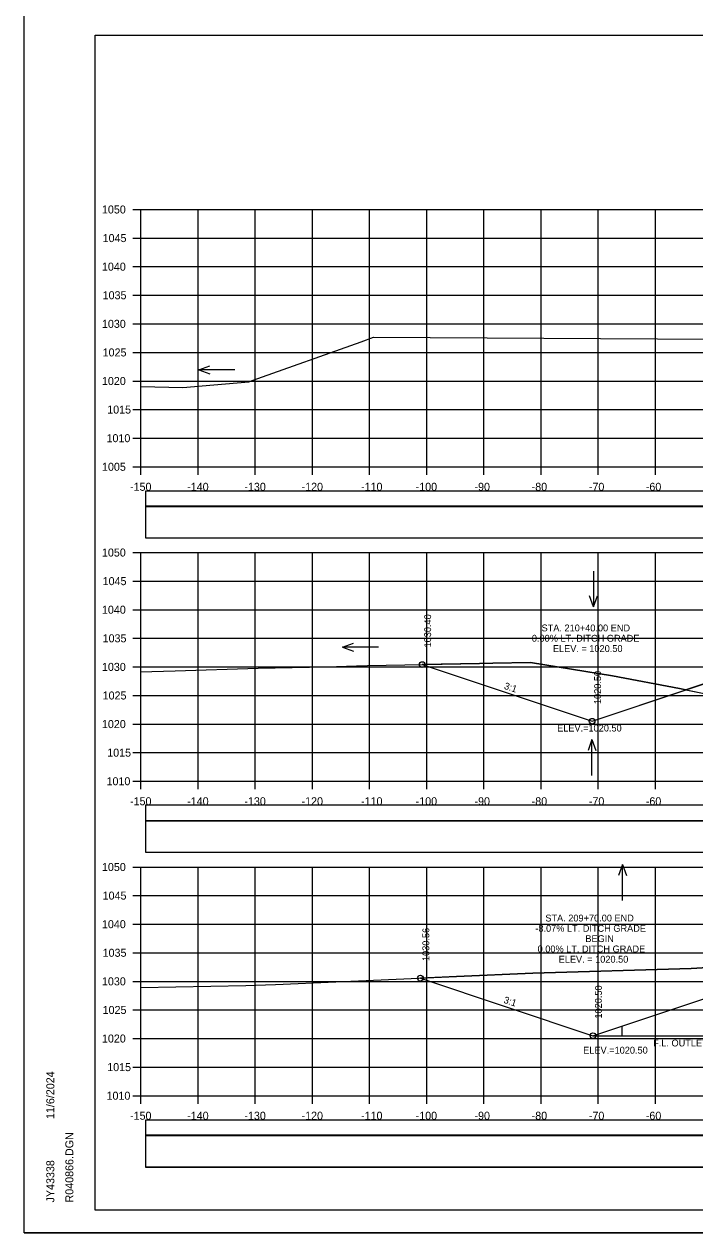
# Model space of a CAD drawing. Extents: x 1370565 to 1374448, y 301010 to 304637.
# Drawn here: x 1373198.4 to 1373315.7, y 301938.3 to 302149.7 of the extents above; entities that cross this region are included whole.
import ezdxf

# ---------------------------------------------------------------- set-up
doc = ezdxf.new("R2010")
doc.units = 0
for name, color, linetype in [('Default', 7, 'Continuous'), ('R_Axis', 7, 'Continuous'), ('R_Axis Annot', 7, 'Continuous'), ('R_Border', 7, 'Continuous'), ('R_Contours', 7, 'Continuous'), ('R_Drive', 7, 'Continuous'), ('R_Exist Surface', 7, 'Continuous'), ('R_Fin Surface', 7, 'Continuous'), ('R_Grid', 7, 'Continuous'), ('R_No Plot', 7, 'Continuous'), ('R_Water', 7, 'Continuous'), ('R_Water Annot', 7, 'Continuous'), ('R_Xsect Elev', 7, 'Continuous'), ('R_Xsect Slope', 7, 'Continuous')]:
    doc.layers.add(name, color=color, linetype=linetype)

msp = doc.modelspace()

# ---------------------------------------------------------------- linework, layer by layer
at = {"layer": 'Default'}
for points in [[(1373219.61, 302065.35), (1373518.02, 302065.35), (1373518.02, 302068.06), (1373219.61, 302068.06)], [(1373219.61, 301955.35), (1373518.02, 301955.35), (1373518.02, 301958.06), (1373219.61, 301958.06)], [(1373219.61, 301949.83), (1373518.02, 301949.83), (1373518.02, 301955.35), (1373219.61, 301955.35)]]:
    msp.add_lwpolyline(points, close=True, dxfattribs=at)
at = {"layer": 'R_Axis'}
for p, q in [((1373217.41, 302117.31), (1373218.81, 302117.31)), ((1373218.81, 302072.31), (1373218.81, 302117.31)), ((1373217.41, 302112.31), (1373218.81, 302112.31)), ((1373217.41, 302107.31), (1373218.81, 302107.31)), ((1373217.41, 302102.31), (1373218.81, 302102.31)), ((1373217.41, 302097.31), (1373218.81, 302097.31)), ((1373217.41, 302092.31), (1373218.81, 302092.31)), ((1373217.41, 302087.31), (1373218.81, 302087.31)), ((1373217.41, 302082.31), (1373218.81, 302082.31)), ((1373217.41, 302077.31), (1373218.81, 302077.31)), ((1373217.41, 302072.31), (1373218.81, 302072.31)), ((1373218.81, 302072.31), (1373518.81, 302072.31)), ((1373218.81, 302070.91), (1373218.81, 302072.31)), ((1373228.81, 302070.91), (1373228.81, 302072.31)), ((1373238.81, 302070.91), (1373238.81, 302072.31)), ((1373248.81, 302070.91), (1373248.81, 302072.31)), ((1373258.81, 302070.91), (1373258.81, 302072.31)), ((1373268.81, 302070.91), (1373268.81, 302072.31)), ((1373278.81, 302070.91), (1373278.81, 302072.31)), ((1373288.81, 302070.91), (1373288.81, 302072.31)), ((1373298.81, 302070.91), (1373298.81, 302072.31)), ((1373308.81, 302070.91), (1373308.81, 302072.31)), ((1373217.41, 302057.31), (1373218.81, 302057.31)), ((1373218.81, 302017.31), (1373218.81, 302057.31)), ((1373217.41, 302052.31), (1373218.81, 302052.31)), ((1373217.41, 302047.31), (1373218.81, 302047.31)), ((1373217.41, 302042.31), (1373218.81, 302042.31)), ((1373217.41, 302037.31), (1373218.81, 302037.31)), ((1373217.41, 302032.31), (1373218.81, 302032.31)), ((1373217.41, 302027.31), (1373218.81, 302027.31)), ((1373217.41, 302022.31), (1373218.81, 302022.31)), ((1373217.41, 302017.31), (1373218.81, 302017.31)), ((1373218.81, 302017.31), (1373518.81, 302017.31)), ((1373218.81, 302015.91), (1373218.81, 302017.31)), ((1373228.81, 302015.91), (1373228.81, 302017.31)), ((1373238.81, 302015.91), (1373238.81, 302017.31)), ((1373248.81, 302015.91), (1373248.81, 302017.31)), ((1373258.81, 302015.91), (1373258.81, 302017.31)), ((1373268.81, 302015.91), (1373268.81, 302017.31)), ((1373278.81, 302015.91), (1373278.81, 302017.31)), ((1373288.81, 302015.91), (1373288.81, 302017.31)), ((1373298.81, 302015.91), (1373298.81, 302017.31)), ((1373308.81, 302015.91), (1373308.81, 302017.31)), ((1373217.41, 302002.31), (1373218.81, 302002.31)), ((1373218.81, 301962.31), (1373218.81, 302002.31)), ((1373217.41, 301997.31), (1373218.81, 301997.31)), ((1373217.41, 301992.31), (1373218.81, 301992.31)), ((1373217.41, 301987.31), (1373218.81, 301987.31)), ((1373217.41, 301982.31), (1373218.81, 301982.31)), ((1373217.41, 301977.31), (1373218.81, 301977.31)), ((1373217.41, 301972.31), (1373218.81, 301972.31)), ((1373217.41, 301967.31), (1373218.81, 301967.31)), ((1373217.41, 301962.31), (1373218.81, 301962.31)), ((1373218.81, 301962.31), (1373518.81, 301962.31)), ((1373218.81, 301960.91), (1373218.81, 301962.31)), ((1373228.81, 301960.91), (1373228.81, 301962.31)), ((1373238.81, 301960.91), (1373238.81, 301962.31)), ((1373248.81, 301960.91), (1373248.81, 301962.31)), ((1373258.81, 301960.91), (1373258.81, 301962.31)), ((1373268.81, 301960.91), (1373268.81, 301962.31)), ((1373278.81, 301960.91), (1373278.81, 301962.31)), ((1373288.81, 301960.91), (1373288.81, 301962.31)), ((1373298.81, 301960.91), (1373298.81, 301962.31)), ((1373308.81, 301960.91), (1373308.81, 301962.31))]:
    msp.add_line(p, q, dxfattribs=at)
at = {"layer": 'R_Border'}
for p, q in [((1373210.81, 302147.77), (1373526.99, 302147.77)), ((1373210.81, 301942.31), (1373210.81, 302147.77)), ((1373210.81, 301942.31), (1373210.81, 301942.31)), ((1373526.99, 301942.31), (1373210.81, 301942.31))]:
    msp.add_line(p, q, dxfattribs=at)
at = {"layer": 'R_Contours'}
msp.add_line((1373314.14, 302033.28), (1373312.99, 302033.51), dxfattribs=at)
for points in [[(1373344.17, 302042.57), (1373339.81, 302041.84), (1373314.14, 302033.28)], [(1373314.14, 302033.28), (1373325.16, 302031.07), (1373334.75, 302029.37), (1373339.38, 302029.2), (1373346.74, 302029.08), (1373349.44, 302029.34), (1373359.32, 302030.03), (1373362, 302030.91), (1373368.81, 302034.6), (1373377.28, 302039.18), (1373395.89, 302041.78)], [(1373312.99, 302033.51), (1373301.31, 302035.74), (1373286.93, 302038.07), (1373280.39, 302037.96), (1373278.04, 302037.9), (1373268.02, 302037.71)], [(1373268.02, 302037.71), (1373297.73, 302027.81), (1373314.14, 302033.28)], [(1373327.48, 301982.68), (1373317.98, 301984.74), (1373315.03, 301984.58), (1373287.35, 301983.75), (1373274.03, 301983.15), (1373267.7, 301982.87)], [(1373267.7, 301982.87), (1373297.88, 301972.81), (1373302.93, 301974.5), (1373317.43, 301979.33)]]:
    msp.add_lwpolyline(points, dxfattribs=at)
msp.add_lwpolyline([(1373219.61, 301949.89), (1373518.02, 301949.89), (1373518.02, 301955.41), (1373219.61, 301955.41)], close=True, dxfattribs=at)
at = {"layer": 'R_Drive'}
for points in [[(1373219.61, 302059.89), (1373518.02, 302059.89), (1373518.02, 302065.41), (1373219.61, 302065.41)], [(1373219.61, 302010.41), (1373518.02, 302010.41), (1373518.02, 302013.11), (1373219.61, 302013.11)], [(1373219.61, 302004.89), (1373518.02, 302004.89), (1373518.02, 302010.41), (1373219.61, 302010.41)]]:
    msp.add_lwpolyline(points, close=True, dxfattribs=at)
at = {"layer": 'R_Exist Surface'}
for points in [[(1373218.81, 302086.33), (1373226.14, 302086.17), (1373229.56, 302086.44), (1373237.69, 302087.19), (1373237.85, 302087.23), (1373238.3, 302087.4), (1373257.32, 302094.17), (1373259.51, 302094.95), (1373319.07, 302094.65), (1373332.97, 302097.2), (1373353.08, 302097.16), (1373372.67, 302097.22), (1373385.56, 302099.4), (1373402.84, 302102.55), (1373408.44, 302102.8), (1373413.14, 302102.97), (1373419.15, 302102.94), (1373423.28, 302102.9), (1373434.93, 302100.74), (1373450.3, 302097.93), (1373478.87, 302097.85), (1373488.98, 302097.85), (1373498.87, 302097.81), (1373518.81, 302097.8)], [(1373218.81, 302036.44), (1373220.71, 302036.51), (1373224.79, 302036.61), (1373239.33, 302037.08), (1373251.3, 302037.33), (1373256.54, 302037.48), (1373258.47, 302037.53), (1373278.04, 302037.9), (1373280.39, 302037.96), (1373286.93, 302038.07), (1373301.31, 302035.74), (1373312.99, 302033.51), (1373325.16, 302031.07)], [(1373218.81, 301981.26), (1373237.16, 301981.6), (1373242.35, 301981.74), (1373274.03, 301983.15), (1373287.35, 301983.75), (1373315.03, 301984.58), (1373317.98, 301984.74)]]:
    msp.add_lwpolyline(points, dxfattribs=at)
at = {"layer": 'R_Fin Surface'}
for points in [[(1373268.02, 302037.71), (1373297.73, 302027.81), (1373339.81, 302041.84), (1373353.81, 302044.18), (1373357.81, 302044.39), (1373368.81, 302044.99), (1373379.81, 302045.59), (1373383.81, 302045.81), (1373397.81, 302043.47), (1373407.3, 302040.31), (1373420.47, 302040.28), (1373443.15, 302039.89), (1373443.6, 302039.81), (1373445.05, 302039.56)], [(1373267.7, 301982.87), (1373267.7, 301982.87), (1373297.88, 301972.81), (1373339.81, 301986.79), (1373339.81, 301986.79), (1373353.81, 301989.12), (1373357.81, 301989.39), (1373368.81, 301990.13), (1373379.81, 301990.87), (1373383.81, 301991.13), (1373397.81, 301988.8), (1373417.36, 301982.29), (1373436.94, 301986.48)]]:
    msp.add_lwpolyline(points, dxfattribs=at)
at = {"layer": 'R_Grid'}
for p, q in [((1373218.81, 302117.31), (1373518.81, 302117.31)), ((1373218.81, 302072.31), (1373218.81, 302117.31)), ((1373228.81, 302072.31), (1373228.81, 302117.31)), ((1373238.81, 302072.31), (1373238.81, 302117.31)), ((1373248.81, 302072.31), (1373248.81, 302117.31)), ((1373258.81, 302072.31), (1373258.81, 302117.31)), ((1373268.81, 302072.31), (1373268.81, 302117.31)), ((1373278.81, 302072.31), (1373278.81, 302117.31)), ((1373288.81, 302072.31), (1373288.81, 302117.31)), ((1373298.81, 302072.31), (1373298.81, 302117.31)), ((1373308.81, 302072.31), (1373308.81, 302117.31)), ((1373218.81, 302112.31), (1373518.81, 302112.31)), ((1373218.81, 302107.31), (1373518.81, 302107.31)), ((1373218.81, 302102.31), (1373518.81, 302102.31)), ((1373218.81, 302097.31), (1373518.81, 302097.31)), ((1373218.81, 302092.31), (1373518.81, 302092.31)), ((1373218.81, 302087.31), (1373518.81, 302087.31)), ((1373218.81, 302082.31), (1373518.81, 302082.31)), ((1373218.81, 302077.31), (1373518.81, 302077.31)), ((1373218.81, 302072.31), (1373518.81, 302072.31)), ((1373218.81, 302057.31), (1373518.81, 302057.31)), ((1373218.81, 302017.31), (1373218.81, 302057.31)), ((1373228.81, 302017.31), (1373228.81, 302057.31)), ((1373238.81, 302017.31), (1373238.81, 302057.31)), ((1373248.81, 302017.31), (1373248.81, 302057.31)), ((1373258.81, 302017.31), (1373258.81, 302057.31)), ((1373268.81, 302017.31), (1373268.81, 302057.31)), ((1373278.81, 302017.31), (1373278.81, 302057.31)), ((1373288.81, 302017.31), (1373288.81, 302057.31)), ((1373298.81, 302017.31), (1373298.81, 302057.31)), ((1373308.81, 302017.31), (1373308.81, 302057.31)), ((1373218.81, 302052.31), (1373518.81, 302052.31)), ((1373218.81, 302047.31), (1373518.81, 302047.31)), ((1373218.81, 302042.31), (1373518.81, 302042.31)), ((1373218.81, 302037.31), (1373518.81, 302037.31)), ((1373218.81, 302032.31), (1373518.81, 302032.31)), ((1373218.81, 302027.31), (1373518.81, 302027.31)), ((1373218.81, 302022.31), (1373518.81, 302022.31)), ((1373218.81, 302017.31), (1373518.81, 302017.31)), ((1373218.81, 302002.31), (1373518.81, 302002.31)), ((1373218.81, 301962.31), (1373218.81, 302002.31)), ((1373228.81, 301962.31), (1373228.81, 302002.31)), ((1373238.81, 301962.31), (1373238.81, 302002.31)), ((1373248.81, 301962.31), (1373248.81, 302002.31)), ((1373258.81, 301962.31), (1373258.81, 302002.31)), ((1373268.81, 301962.31), (1373268.81, 302002.31)), ((1373278.81, 301962.31), (1373278.81, 302002.31)), ((1373288.81, 301962.31), (1373288.81, 302002.31)), ((1373298.81, 301962.31), (1373298.81, 302002.31)), ((1373308.81, 301962.31), (1373308.81, 302002.31)), ((1373218.81, 301997.31), (1373518.81, 301997.31)), ((1373218.81, 301992.31), (1373518.81, 301992.31)), ((1373218.81, 301987.31), (1373518.81, 301987.31)), ((1373218.81, 301982.31), (1373518.81, 301982.31)), ((1373218.81, 301977.31), (1373518.81, 301977.31)), ((1373218.81, 301972.31), (1373518.81, 301972.31)), ((1373218.81, 301967.31), (1373518.81, 301967.31)), ((1373218.81, 301962.31), (1373518.81, 301962.31))]:
    msp.add_line(p, q, dxfattribs=at)
at = {"layer": 'R_No Plot'}
msp.add_line((1373198.41, 301938.33), (1373531.75, 301938.33), dxfattribs=at)
for points in [[(1373198.41, 302151.67), (1373531.75, 302151.67), (1373531.75, 301938.33), (1373198.41, 301938.33)], [(1373444.73, 302147.77), (1373464.35, 302147.77), (1373464.35, 302137.89), (1373480.47, 302137.89), (1373503.67, 302137.89), (1373503.67, 302105.22), (1373526.87, 302105.22), (1373526.99, 301942.31), (1373210.81, 301942.31), (1373210.81, 302147.77)]]:
    msp.add_lwpolyline(points, close=True, dxfattribs=at)
for centre in [(1373268.02, 302037.71), (1373297.73, 302027.81), (1373267.7, 301982.87), (1373297.88, 301972.81)]:
    msp.add_circle(centre, 0.5, dxfattribs=at)
at = {"layer": 'R_Water'}
for p, q in [((1373302.93, 301974.5), (1373302.93, 301972.81)), ((1373297.88, 301972.81), (1373318.43, 301972.81))]:
    msp.add_line(p, q, dxfattribs=at)
at = {"layer": 'R_Water Annot'}
for p, q in [((1373228.97, 302089.25), (1373230.89, 302089.95)), ((1373235.25, 302089.25), (1373228.97, 302089.25)), ((1373228.97, 302089.25), (1373230.89, 302088.55)), ((1373297.99, 302054.08), (1373297.99, 302047.8)), ((1373297.99, 302047.8), (1373297.29, 302049.72)), ((1373297.99, 302047.8), (1373298.69, 302049.72)), ((1373254.09, 302040.76), (1373256.02, 302041.46)), ((1373260.38, 302040.76), (1373254.09, 302040.76)), ((1373254.09, 302040.76), (1373256.02, 302040.06)), ((1373297.7, 302024.6), (1373297.02, 302022.68)), ((1373297.7, 302018.32), (1373297.7, 302024.6)), ((1373297.7, 302024.6), (1373298.39, 302022.68)), ((1373303.05, 302002.76), (1373302.35, 302000.84)), ((1373303.05, 301996.48), (1373303.05, 302002.76)), ((1373303.05, 302002.76), (1373303.75, 302000.84))]:
    msp.add_line(p, q, dxfattribs=at)

# ---------------------------------------------------------------- texts
at = {"layer": 'R_Axis Annot'}
for s, p in [('1050', (1373212.01, 302116.61)), ('1045', (1373212.13, 302111.61)), ('1040', (1373212.01, 302106.61)), ('1035', (1373212.13, 302101.61)), ('1030', (1373212.01, 302096.61)), ('1025', (1373212.13, 302091.61)), ('1020', (1373212.01, 302086.61)), ('1015', (1373212.93, 302081.61)), ('1010', (1373212.81, 302076.61)), ('1005', (1373212.02, 302071.61)), ('-150', (1373216.92, 302068.11)), ('-140', (1373226.92, 302068.11)), ('-130', (1373236.92, 302068.11)), ('-120', (1373246.92, 302068.11)), ('-110', (1373257.32, 302068.11)), ('-100', (1373266.87, 302068.11)), ('-90', (1373277.16, 302068.11)), ('-80', (1373287.16, 302068.11)), ('-70', (1373297.16, 302068.11)), ('-60', (1373307.12, 302068.11)), ('1050', (1373212.01, 302056.61)), ('1045', (1373212.13, 302051.61)), ('1040', (1373212.01, 302046.61)), ('1035', (1373212.13, 302041.61)), ('1030', (1373212.01, 302036.61)), ('1025', (1373212.13, 302031.61)), ('1020', (1373212.01, 302026.61)), ('1015', (1373212.93, 302021.61)), ('1010', (1373212.81, 302016.61)), ('-150', (1373216.92, 302013.11)), ('-140', (1373226.92, 302013.11)), ('-130', (1373236.92, 302013.11)), ('-120', (1373246.92, 302013.11)), ('-110', (1373257.32, 302013.11)), ('-100', (1373266.87, 302013.11)), ('-90', (1373277.16, 302013.11)), ('-80', (1373287.16, 302013.11)), ('-70', (1373297.16, 302013.11)), ('-60', (1373307.12, 302013.11)), ('1050', (1373212.01, 302001.61)), ('1045', (1373212.13, 301996.61)), ('1040', (1373212.01, 301991.61)), ('1035', (1373212.13, 301986.61)), ('1030', (1373212.01, 301981.61)), ('1025', (1373212.13, 301976.61)), ('1020', (1373212.01, 301971.61)), ('1015', (1373212.93, 301966.61)), ('1010', (1373212.81, 301961.61)), ('-150', (1373216.92, 301958.11)), ('-140', (1373226.92, 301958.11)), ('-130', (1373236.92, 301958.11)), ('-120', (1373246.92, 301958.11)), ('-110', (1373257.32, 301958.11)), ('-100', (1373266.87, 301958.11)), ('-90', (1373277.16, 301958.11)), ('-80', (1373287.16, 301958.11)), ('-70', (1373297.16, 301958.11)), ('-60', (1373307.12, 301958.11))]:
    msp.add_text(s, height=1.4, dxfattribs=at).set_placement(p)
at = {"layer": 'R_Border'}
for s, p in [('11/6/2024', (1373203.68, 301958.24)), ('R040866.DGN', (1373207.01, 301943.64)), ('JY43338', (1373203.68, 301943.64))]:
    msp.add_text(s, height=1.4, rotation=90, dxfattribs=at).set_placement(p)
at = {"layer": 'R_Water Annot'}
msp.add_text('F.L. OUTLET=1020.50', height=1.2, dxfattribs=at).set_placement((1373308.4, 301970.93))
at = {"layer": 'R_Xsect Elev'}
for s, p in [('1030.40', (1373269.57, 302040.71)), ('1020.50', (1373299.28, 302030.81)), ('1030.56', (1373269.25, 301985.87)), ('1020.50', (1373299.43, 301975.81))]:
    msp.add_text(s, height=1.2, rotation=90, dxfattribs=at).set_placement(p)
for s, p in [('0.00% LT. DITCH GRADE', (1373287.19, 302041.72)), ('STA. 210+40.00 END ', (1373288.89, 302043.52)), ('ELEV. = 1020.50', (1373290.87, 302039.92)), ('ELEV.=1020.50', (1373291.61, 302026.01)), ('-8.07% LT. DITCH GRADE', (1373287.8, 301990.98)), ('STA. 209+70.00 END', (1373289.55, 301992.78)), ('BEGIN', (1373296.54, 301989.18)), ('0.00% LT. DITCH GRADE', (1373288.2, 301987.38)), ('ELEV. = 1020.50', (1373291.88, 301985.58)), ('ELEV.=1020.50', (1373296.17, 301969.67))]:
    msp.add_text(s, height=1.2, dxfattribs=at).set_placement(p)
at = {"layer": 'R_Xsect Slope'}
for p in [(1373282.24, 302033.5), (1373282.16, 301978.58)]:
    msp.add_text('3:1', height=1.2, rotation=341.5668, dxfattribs=at).set_placement(p)

doc.saveas('drawing.dxf')
